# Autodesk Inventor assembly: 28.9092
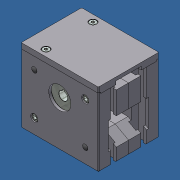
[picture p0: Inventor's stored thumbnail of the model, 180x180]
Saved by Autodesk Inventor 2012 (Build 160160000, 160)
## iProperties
Created: 2007-04
Part Number: 28.9092
Document SubType Name: Assembly
Designer: Andy Moles
Description: T90 PULLEY 1/2" BORE & KEY
Author: Andy Moles
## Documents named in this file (9)
- C:\Andys Backup Data\ANDY'S INVENTOR\INVENTOR LIBRARIES\PARTS LIBRARY\READY FOR USE MODULES LR\28.9092  T90 PULLEY .5 BORE-KEY .iam
- C:\Andys Backup Data\ANDY'S INVENTOR\INVENTOR LIBRARIES\PARTS LIBRARY\LINEAR MODULE LMZ 90\SUBCOMPONENTS\28.0082 T90 BEARING 35X62X14.ipt
- C:\Andys Backup Data\ANDY'S INVENTOR\INVENTOR LIBRARIES\PARTS LIBRARY\READY FOR USE MODULES LR\SUBCOMPONENTS\28.0081 T90 TOP.ipt
- C:\Andys Backup Data\ANDY'S INVENTOR\INVENTOR LIBRARIES\PARTS LIBRARY\FASTENING ELEMENTS\SCREWS CAP\21.1238 M6X16.ipt
- C:\Andys Backup Data\ANDY'S INVENTOR\INVENTOR LIBRARIES\PARTS LIBRARY\LINEAR MODULE LMZ 90\SUBCOMPONENTS\SHCS M6X55 HIGH HEAD DIN 912.ipt
- C:\Andys Backup Data\ANDY'S INVENTOR\INVENTOR LIBRARIES\PARTS LIBRARY\READY FOR USE MODULES LR\SUBCOMPONENTS\28.0080_3 T90 LEFT SIDE 33mm HOLE.ipt
- C:\Andys Backup Data\ANDY'S INVENTOR\INVENTOR LIBRARIES\PARTS LIBRARY\READY FOR USE MODULES LR\SUBCOMPONENTS\28.0080_4 T90 RIGHT SIDE 33mm HOLE.ipt
- C:\Andys Backup Data\ANDY'S INVENTOR\INVENTOR LIBRARIES\PARTS LIBRARY\END CAPS\22.1203 HOLE CAP M6.ipt
- C:\Andys Backup Data\ANDY'S INVENTOR\INVENTOR LIBRARIES\PARTS LIBRARY\READY FOR USE MODULES LR\SUBCOMPONENTS\28.9092_1 T90 PULLEY .5 BORE-KEY.ipt
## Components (16 placed, 8 different names)
1. 28.9092_1 T90 PULLEY .5 BORE-KEY:1 — Insert:1, Insert:2, Mate:6, Mate:9, Angle:2
2. 28.0082 T90 BEARING 35X62X14:1 — Insert:1
3. 28.0082 T90 BEARING 35X62X14:2 — Insert:2, Mate:10
4. 28.0080_4 T90 RIGHT SIDE 33mm HOLE:1 — Angle:1, Flush:3, Mate:5, Insert:5, Insert:6, Insert:11, Insert:12, Flush:6, Mate:8, Flush:7
5. 28.0080_3 T90 LEFT SIDE 33mm HOLE:1 — Flush:3, Flush:4, Flush:5, Insert:7, Insert:8, Insert:9, Insert:10, Mate:8, Mate:10
6. 28.0081 T90 TOP:1 — Flush:4, Mate:5, Flush:5, Insert:3, Insert:4, Flush:7
7. 21.1238  M6X16 SHCS:1 — Insert:3
8. 21.1238  M6X16 SHCS:2 — Insert:4
9. M6X55 CAP SCREW HIGH HEAD:1 — Insert:5
10. M6X55 CAP SCREW HIGH HEAD:2 — Insert:6
11. M6X55 CAP SCREW HIGH HEAD:3 — Insert:8
12. M6X55 CAP SCREW HIGH HEAD:4 — Insert:7
13. 22.1203 HOLE CAP M6:1 — Insert:9
14. 22.1203 HOLE CAP M6:2 — Insert:10
15. 22.1203 HOLE CAP M6:3 — Insert:11
16. 22.1203 HOLE CAP M6:4 — Insert:12
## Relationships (24: Insert 12, Flush 5, Mate 5, Angle 2)
- Insert:1: 28.9092_1 T90 PULLEY .5 BORE-KEY:1 ↔ 28.0082 T90 BEARING 35X62X14:1
- Insert:2: 28.9092_1 T90 PULLEY .5 BORE-KEY:1 ↔ 28.0082 T90 BEARING 35X62X14:2
- Angle:1: 28.0080_4 T90 RIGHT SIDE 33mm HOLE:1
- Flush:3: 28.0080_4 T90 RIGHT SIDE 33mm HOLE:1 ↔ 28.0080_3 T90 LEFT SIDE 33mm HOLE:1
- Flush:4: 28.0080_3 T90 LEFT SIDE 33mm HOLE:1 ↔ 28.0081 T90 TOP:1
- Mate:5: 28.0080_4 T90 RIGHT SIDE 33mm HOLE:1 ↔ 28.0081 T90 TOP:1
- Flush:5: 28.0080_3 T90 LEFT SIDE 33mm HOLE:1 ↔ 28.0081 T90 TOP:1
- Insert:3: 28.0081 T90 TOP:1 ↔ 21.1238  M6X16 SHCS:1
- Insert:4: 28.0081 T90 TOP:1 ↔ 21.1238  M6X16 SHCS:2
- Insert:5: 28.0080_4 T90 RIGHT SIDE 33mm HOLE:1 ↔ M6X55 CAP SCREW HIGH HEAD:1
- Insert:6: 28.0080_4 T90 RIGHT SIDE 33mm HOLE:1 ↔ M6X55 CAP SCREW HIGH HEAD:2
- Insert:7: 28.0080_3 T90 LEFT SIDE 33mm HOLE:1 ↔ M6X55 CAP SCREW HIGH HEAD:4
- Insert:8: 28.0080_3 T90 LEFT SIDE 33mm HOLE:1 ↔ M6X55 CAP SCREW HIGH HEAD:3
- Insert:9: 28.0080_3 T90 LEFT SIDE 33mm HOLE:1 ↔ 22.1203 HOLE CAP M6:1
- Insert:10: 28.0080_3 T90 LEFT SIDE 33mm HOLE:1 ↔ 22.1203 HOLE CAP M6:2
- Insert:11: 28.0080_4 T90 RIGHT SIDE 33mm HOLE:1 ↔ 22.1203 HOLE CAP M6:3
- Insert:12: 28.0080_4 T90 RIGHT SIDE 33mm HOLE:1 ↔ 22.1203 HOLE CAP M6:4
- Mate:6: 28.9092_1 T90 PULLEY .5 BORE-KEY:1
- Flush:6: 28.0080_4 T90 RIGHT SIDE 33mm HOLE:1
- Mate:8: 28.0080_4 T90 RIGHT SIDE 33mm HOLE:1 ↔ 28.0080_3 T90 LEFT SIDE 33mm HOLE:1
- Mate:9: 28.9092_1 T90 PULLEY .5 BORE-KEY:1
- Angle:2: 28.9092_1 T90 PULLEY .5 BORE-KEY:1
- Mate:10: 28.0082 T90 BEARING 35X62X14:2 ↔ 28.0080_3 T90 LEFT SIDE 33mm HOLE:1
- Flush:7: 28.0080_4 T90 RIGHT SIDE 33mm HOLE:1 ↔ 28.0081 T90 TOP:1
